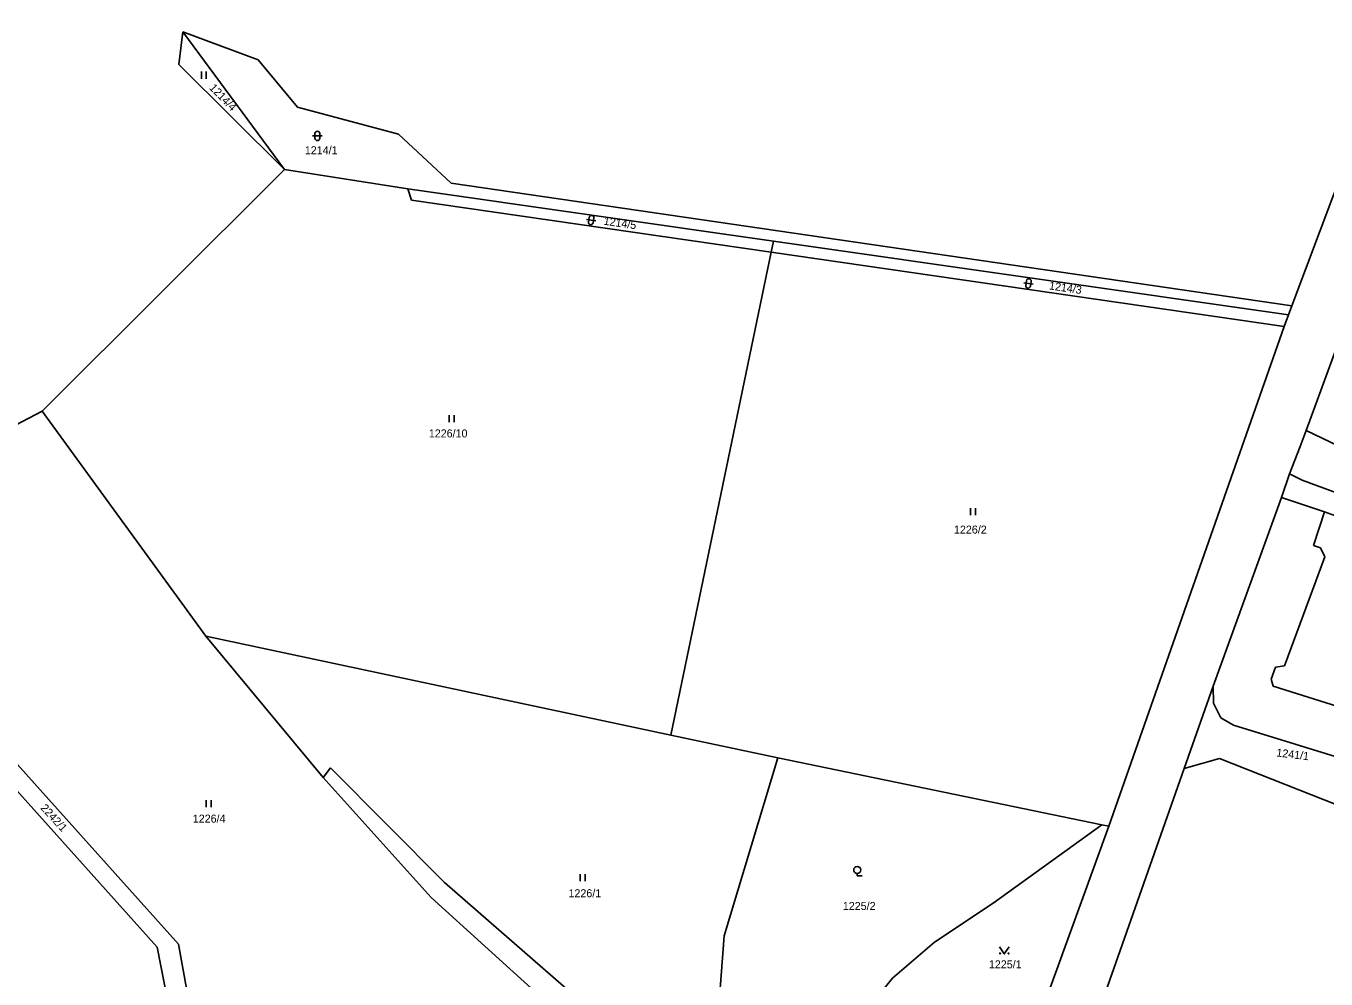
# Model space of a CAD drawing. Extents: x -717507 to -715515, y -957700 to -954941.
# Drawn here: x -717129.5 to -716853.4, y -956934.7 to -956732.3 of the extents above; entities that cross this region are included whole.
import ezdxf

# ---------------------------------------------------------------- set-up
doc = ezdxf.new("R2010")
doc.units = 0
for name, color, linetype in [('Hranice parcel', 7, 'Continuous'), ('Parcelní čísla', 7, 'Continuous'), ('Značky kultur', 7, 'Continuous')]:
    doc.layers.add(name, color=color, linetype=linetype)

msp = doc.modelspace()

# ---------------------------------------------------------------- linework, layer by layer
at = {"layer": 'Hranice parcel'}
for points in [[(-716860.64, -956791.7), (-716822.01, -956689.04)], [(-717096.18, -956733.53), (-717097.04, -956740.43)], [(-717096.18, -956733.53), (-717080.19, -956739.49)], [(-717096.18, -956733.53), (-717074.6, -956762.76)], [(-717097.04, -956740.43), (-717074.6, -956762.76)], [(-717080.19, -956739.49), (-717071.83, -956749.53)], [(-716830.72, -956744.98), (-716857.59, -956818.19)], [(-717071.83, -956749.53), (-717050.37, -956755.26)], [(-717050.37, -956755.26), (-717039.2, -956765.67)], [(-717074.6, -956762.76), (-717126.11, -956814.08)], [(-717074.6, -956762.76), (-717048.41, -956766.85)], [(-717048.41, -956766.85), (-717047.63, -956769.24)], [(-716970.7, -956777.97), (-717048.41, -956766.85)], [(-716860.64, -956791.7), (-717039.2, -956765.67)], [(-717047.63, -956769.24), (-716971.19, -956780.3)], [(-716971.19, -956780.3), (-716970.7, -956777.97)], [(-716861.34, -956793.62), (-716970.7, -956777.97)], [(-716992.52, -956882.86), (-716971.19, -956780.3)], [(-716971.19, -956780.3), (-716862.22, -956796.07)], [(-716861.34, -956793.62), (-716860.64, -956791.7)], [(-716862.22, -956796.07), (-716861.34, -956793.62)], [(-716899.47, -956902.24), (-716862.22, -956796.07)], [(-717167.3, -956835.66), (-717126.11, -956814.08)], [(-717126.11, -956814.08), (-717091.31, -956861.83)], [(-716858.87, -956821.56), (-716857.59, -956818.19)], [(-716857.59, -956818.19), (-716850.81, -956821.41)], [(-716861.11, -956827.41), (-716858.87, -956821.56)], [(-716861.11, -956827.41), (-716862.81, -956832.43)], [(-716858.43, -956828.76), (-716861.11, -956827.41)], [(-716836.76, -956836.72), (-716858.43, -956828.76)], [(-716862.81, -956832.43), (-716877.3, -956872.46)], [(-716862.81, -956832.43), (-716853.71, -956835.49)], [(-716853.71, -956835.49), (-716856.01, -956842.6)], [(-716853.71, -956835.49), (-716850.57, -956836.62)], [(-716856.01, -956842.6), (-716854.54, -956843.09)], [(-716854.54, -956843.09), (-716853.63, -956844.99)], [(-716853.63, -956844.99), (-716862.17, -956868.18)], [(-717066.37, -956891.85), (-717091.31, -956861.83)], [(-716992.52, -956882.86), (-717091.31, -956861.83)], [(-716864.98, -956870.99), (-716864.07, -956868.48)], [(-716864.07, -956868.48), (-716862.17, -956868.18)], [(-717097.11, -956927.29), (-717148.57, -956869.93)], [(-716864.98, -956870.99), (-716864.61, -956872.51)], [(-716877.3, -956872.46), (-716883.47, -956889.98)], [(-716877.3, -956872.46), (-716877.24, -956876.12)], [(-716864.61, -956872.51), (-716848.38, -956877.58)], [(-717101.64, -956927.88), (-717148.05, -956876.22)], [(-716877.24, -956876.12), (-716875.72, -956879.23)], [(-716875.72, -956879.23), (-716873.03, -956880.76)], [(-716969.78, -956887.7), (-716992.52, -956882.86)], [(-716873.03, -956880.76), (-716846.8, -956888.82)], [(-716969.78, -956887.7), (-716981.19, -956925.52)], [(-716969.78, -956887.7), (-716900.97, -956901.94)], [(-716883.47, -956889.98), (-716875.96, -956887.84)], [(-716875.96, -956887.84), (-716848.02, -956898.9)], [(-717066.37, -956891.85), (-717064.81, -956889.84)], [(-717064.81, -956889.84), (-717040.64, -956914.21)], [(-716883.47, -956889.98), (-716922.85, -957001.88)], [(-717066.37, -956891.85), (-717043.43, -956917.39)], [(-716900.97, -956901.94), (-716924.06, -956918.59)], [(-716899.47, -956902.24), (-716913.71, -956941.41)], [(-716900.97, -956901.94), (-716899.47, -956902.24)], [(-717040.64, -956914.21), (-717010.38, -956940.53)], [(-717020.68, -956938), (-717043.43, -956917.39)], [(-716936.55, -956926.88), (-716924.06, -956918.59)], [(-716983.22, -956951.73), (-716981.19, -956925.52)], [(-716945.43, -956934.46), (-716936.55, -956926.88)], [(-717101.64, -956927.88), (-717094.06, -956966.51)], [(-717090.31, -956964.95), (-717097.11, -956927.29)], [(-716949.89, -956940.04), (-716945.43, -956934.46)]]:
    msp.add_lwpolyline(points, dxfattribs=at)
at = {"layer": 'Značky kultur'}
for points in [[(-717092.27, -956743.48), (-717092.27, -956741.98)], [(-717091.23, -956743.48), (-717091.23, -956741.98)], [(-717068.63, -956755.63), (-717066.63, -956755.63)], [(-717068.13, -956756.13), (-717068.13, -956755.13)], [(-717067.13, -956755.13), (-717067.13, -956756.13)], [(-717010.45, -956773.35), (-717008.47, -956773.63)], [(-717010.02, -956773.91), (-717009.88, -956772.92)], [(-717008.89, -956773.07), (-717009.03, -956774.06)], [(-716917.56, -956786.81), (-716915.58, -956787.09)], [(-716917.13, -956787.37), (-716916.99, -956786.38)], [(-716916, -956786.53), (-716916.14, -956787.52)], [(-717039.63, -956816.4), (-717039.63, -956814.9)], [(-717038.59, -956816.4), (-717038.59, -956814.9)], [(-716928.89, -956836.18), (-716928.89, -956834.68)], [(-716927.85, -956836.18), (-716927.85, -956834.68)], [(-717091.23, -956898.21), (-717091.23, -956896.71)], [(-717090.19, -956898.21), (-717090.19, -956896.71)], [(-717011.79, -956913.92), (-717011.79, -956912.42)], [(-717010.75, -956913.92), (-717010.75, -956912.42)], [(-716952.94, -956912.26), (-716952.94, -956912.76), (-716951.92, -956912.76)], [(-716922.7, -956927.84), (-716921.7, -956929.34), (-716920.7, -956927.84)]]:
    msp.add_lwpolyline(points, dxfattribs=at)
for centre, radius in [((-716952.94, -956911.51), 0.75), ((-716922.6, -956929.24), 0.1), ((-716920.8, -956929.24), 0.1)]:
    msp.add_circle(centre, radius, dxfattribs=at)
for centre, radius, start, end in [((-717067.63, -956755.13), 0.5, 0.101, 180.0014), ((-717067.63, -956756.13), 0.5, 180.1024, 0.0029), ((-717009.53, -956773.99), 0.499, 171.81, 351.7104), ((-717009.38, -956773), 0.5, 351.3403, 171.7255), ((-716916.49, -956786.46), 0.5, 351.3403, 171.7255), ((-716916.64, -956787.45), 0.499, 171.81, 351.7104)]:
    msp.add_arc(centre, radius, start, end, dxfattribs=at)

# ---------------------------------------------------------------- texts
at = {"layer": 'Parcelní čísla'}
for s, rotation, p in [('1214/4', 314.3025, (-717090.7, -956745.53)), ('1214/5', 351.7028, (-717006.89, -956774.46)), ('1214/3', 351.7028, (-716912.27, -956788.21)), ('1241/1', 353.1028, (-716863.98, -956887.39)), ('2242/1', 312.6025, (-717126.54, -956898.45))]:
    msp.add_text(s, height=1.7, rotation=rotation, dxfattribs=at).set_placement(p)
for s, p in [('1214/1', (-717070.29, -956759.52)), ('1226/10', (-717043.95, -956819.66)), ('1226/2', (-716932.39, -956840.08)), ('1226/4', (-717094.09, -956901.46)), ('1226/1', (-717014.28, -956917.31)), ('1225/2', (-716956, -956920.01)), ('1225/1', (-716924.97, -956932.41))]:
    msp.add_text(s, height=1.7, dxfattribs=at).set_placement(p)

doc.saveas('drawing.dxf')
